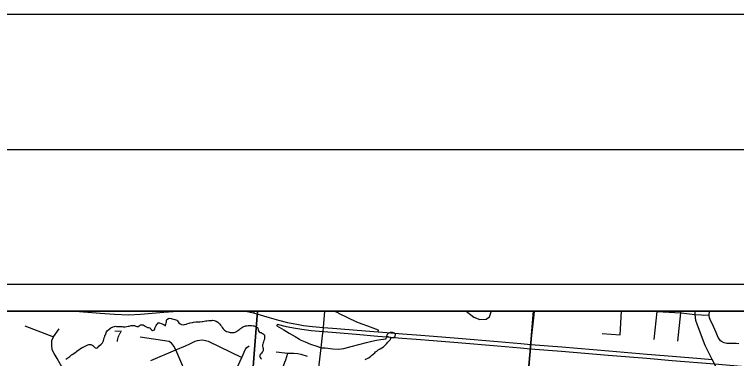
# Model space of a CAD drawing. Extents: x 0 to 34, y 0 to 22.
# Drawn here: x 3.964 to 6.638, y 20.725 to 22 of the extents above; entities that cross this region are included whole.
import ezdxf

# ---------------------------------------------------------------- set-up
doc = ezdxf.new("R2010")
doc.units = 0
for name, color, linetype in [('Default', 7, 'Continuous'), ('GM_X_Interchange_Ramps', 7, 'Continuous'), ('GM_X_Minor_River', 7, 'Continuous'), ('GM_X_Section_Text', 7, 'Continuous'), ('GM_X_State_Route', 7, 'Continuous'), ('GM_X_Township_Road', 7, 'Continuous'), ('SH_Border', 7, 'Continuous'), ('SH_Cut_Line', 7, 'Continuous'), ('SH_Data', 7, 'Continuous')]:
    doc.layers.add(name, color=color, linetype=linetype)

msp = doc.modelspace()

# ---------------------------------------------------------------- linework, layer by layer
at = {"layer": 'Default'}
for points in [[(4.8644, 20.9), (3.8452, 20.9), (3.806, 20.3918), (4.818, 20.3144)], [(5.8864, 20.9), (4.8644, 20.9), (4.818, 20.3144), (5.8084, 20.2412), (5.8307, 20.238)], [(6.92, 20.9), (5.8864, 20.9), (5.8307, 20.238), (6.8362, 20.1611), (6.8487, 20.1601)]]:
    msp.add_lwpolyline(points, close=True, dxfattribs=at)
at = {"layer": 'GM_X_Interchange_Ramps'}
for points in [[(4.9242, 20.9), (4.9177, 20.8994), (4.8932, 20.899), (4.8515, 20.8985), (4.8496, 20.8935)], [(5.1658, 20.8922), (5.1626, 20.8938), (5.1475, 20.9)], [(5.3117, 20.824), (5.3122, 20.8296), (5.2732, 20.8442), (5.2521, 20.8517), (5.2319, 20.8599), (5.1658, 20.8922)], [(4.9373, 20.8524), (4.9362, 20.8459), (4.9616, 20.8314), (4.9818, 20.8187), (5.0038, 20.8064), (5.0198, 20.7963)], [(5.0198, 20.7963), (5.0226, 20.7945), (5.041, 20.7862), (5.0604, 20.7779), (5.0836, 20.7709), (5.0995, 20.7643)], [(5.0995, 20.7643), (5.1148, 20.7647), (5.1433, 20.7603), (5.1639, 20.7594), (5.1845, 20.7616), (5.2113, 20.7687), (5.2679, 20.784), (5.2881, 20.7893), (5.3052, 20.7928), (5.3206, 20.7954), (5.3412, 20.7981), (5.3419, 20.8057)]]:
    msp.add_lwpolyline(points, dxfattribs=at)
at = {"layer": 'GM_X_Minor_River'}
for points in [[(4.4934, 20.8536), (4.4969, 20.8569), (4.5011, 20.8564), (4.5079, 20.8546), (4.5173, 20.8509), (4.5232, 20.8453), (4.5253, 20.8517), (4.5262, 20.8566), (4.5267, 20.8593), (4.5274, 20.8665), (4.5282, 20.8691), (4.5341, 20.8735), (4.5372, 20.8737), (4.5447, 20.8731), (4.5485, 20.8718), (4.5583, 20.8695), (4.5613, 20.8683), (4.5651, 20.8666), (4.5684, 20.8646), (4.571, 20.8611), (4.5731, 20.8576), (4.5775, 20.8532), (4.5828, 20.8507), (4.5911, 20.85), (4.5938, 20.8503), (4.5999, 20.852), (4.603, 20.853), (4.6111, 20.8558), (4.615, 20.8564), (4.6234, 20.8584), (4.6273, 20.8594), (4.6361, 20.8609), (4.6403, 20.8612), (4.6486, 20.8609), (4.6525, 20.8611), (4.6597, 20.862), (4.6624, 20.8622), (4.667, 20.8632), (4.6735, 20.8645), (4.6766, 20.8648), (4.6838, 20.8653), (4.6873, 20.8655), (4.6945, 20.866), (4.6972, 20.8663), (4.7036, 20.8657), (4.7116, 20.8631), (4.7171, 20.8591), (4.7234, 20.8531), (4.7277, 20.848), (4.7307, 20.8441), (4.7339, 20.8398), (4.7372, 20.8347), (4.7415, 20.8296), (4.749, 20.8252), (4.7558, 20.8234), (4.7592, 20.8221), (4.7633, 20.8216), (4.7682, 20.8207), (4.7732, 20.8212), (4.7774, 20.8218), (4.7813, 20.8228), (4.7859, 20.8246), (4.7886, 20.8264), (4.7914, 20.8286), (4.7945, 20.8311), (4.7973, 20.8329), (4.8016, 20.8366), (4.8086, 20.8412), (4.814, 20.8433), (4.8175, 20.8443), (4.8202, 20.8458), (4.8248, 20.8464), (4.8298, 20.8469), (4.834, 20.8468), (4.8393, 20.847), (4.8419, 20.8469), (4.848, 20.8463), (4.8522, 20.8453), (4.8548, 20.8445), (4.8593, 20.842), (4.8642, 20.84), (4.8656, 20.8369), (4.8665, 20.8303), (4.8675, 20.8269), (4.87, 20.8234), (4.8742, 20.8217), (4.8775, 20.8208), (4.8805, 20.8188), (4.8832, 20.8179), (4.8858, 20.8167), (4.8887, 20.8132), (4.8897, 20.8105), (4.8899, 20.8055), (4.8902, 20.8013), (4.8896, 20.7964), (4.8883, 20.7915), (4.8862, 20.7862), (4.8849, 20.7828), (4.8836, 20.7783), (4.8831, 20.7749), (4.8833, 20.7703)], [(4.1545, 20.7219), (4.162, 20.7273), (4.169, 20.7324), (4.1757, 20.7379), (4.1784, 20.7397), (4.1846, 20.7429), (4.1925, 20.749), (4.1956, 20.7516), (4.2039, 20.7581), (4.207, 20.7603), (4.2128, 20.7639), (4.2156, 20.7657), (4.221, 20.7685), (4.2237, 20.7692), (4.2284, 20.7721), (4.2365, 20.7752), (4.2392, 20.7766), (4.2438, 20.7772), (4.2464, 20.7764), (4.2502, 20.7755), (4.2547, 20.7726), (4.2587, 20.7694), (4.2631, 20.7647), (4.2677, 20.7634), (4.2715, 20.7648), (4.2782, 20.7714), (4.2857, 20.7783), (4.2905, 20.7831), (4.2934, 20.7906), (4.2955, 20.7962), (4.2968, 20.8011), (4.2973, 20.8038), (4.2986, 20.8068), (4.2994, 20.8098), (4.3015, 20.8128), (4.3027, 20.8158), (4.3049, 20.8233), (4.3073, 20.827), (4.3132, 20.8329), (4.3207, 20.8383), (4.3296, 20.8426), (4.3346, 20.8439), (4.3388, 20.8441), (4.3422, 20.844), (4.3468, 20.8435), (4.3509, 20.8429), (4.3627, 20.8429), (4.3673, 20.8423), (4.3719, 20.8425), (4.3745, 20.8428), (4.3807, 20.8433), (4.3856, 20.8443), (4.3891, 20.8449), (4.3929, 20.8456), (4.3964, 20.8466), (4.4006, 20.8472), (4.4044, 20.8474), (4.4082, 20.8469), (4.4108, 20.8457), (4.4138, 20.8448), (4.4176, 20.8439), (4.4218, 20.843), (4.4257, 20.8459), (4.4288, 20.8477), (4.4315, 20.8491), (4.4376, 20.8496), (4.4407, 20.8495), (4.4485, 20.8446), (4.4567, 20.8402), (4.4601, 20.8393), (4.4639, 20.8384), (4.4665, 20.8383), (4.4679, 20.8352), (4.4716, 20.8312), (4.4757, 20.8292), (4.4795, 20.8294), (4.4826, 20.8312), (4.4835, 20.8346), (4.484, 20.8376), (4.4861, 20.8417), (4.4886, 20.8477), (4.491, 20.8503), (4.4934, 20.8536)], [(5.3594, 20.8025), (5.3697, 20.8028), (5.3716, 20.8047), (5.3736, 20.8069), (5.3757, 20.8144), (5.372, 20.8191), (5.3637, 20.8208), (5.3554, 20.8218), (5.3484, 20.817), (5.3445, 20.8141), (5.343, 20.8119), (5.3421, 20.8096)], [(5.3421, 20.8096), (5.3455, 20.8073), (5.3496, 20.8056), (5.3594, 20.8025)], [(5.3252, 20.7647), (5.3303, 20.7683), (5.3346, 20.772), (5.3378, 20.7749), (5.3425, 20.7797), (5.3473, 20.7856), (5.3524, 20.7903), (5.3552, 20.7937), (5.3572, 20.7962), (5.3577, 20.7997), (5.3594, 20.8023), (5.3594, 20.8025)], [(4.8833, 20.7703), (4.8843, 20.7654), (4.8853, 20.7623), (4.8858, 20.7569), (4.8857, 20.7535), (4.8841, 20.7509), (4.8817, 20.7483), (4.8789, 20.7446), (4.8754, 20.7413), (4.8726, 20.7376), (4.8721, 20.7346), (4.8731, 20.7315), (4.8745, 20.7284), (4.8763, 20.7249), (4.8788, 20.7218)], [(5.2634, 20.7213), (5.2759, 20.7277), (5.2809, 20.7309), (5.2864, 20.7357), (5.2931, 20.7415), (5.2986, 20.7455), (5.3018, 20.7492), (5.3065, 20.7524), (5.3116, 20.7564), (5.3182, 20.7611), (5.3252, 20.7647)]]:
    msp.add_lwpolyline(points, dxfattribs=at)
at = {"layer": 'GM_X_State_Route'}
for points in [[(4.1953, 20.9), (4.2049, 20.8992), (4.282, 20.8929), (4.3352, 20.8891), (4.3872, 20.8872), (4.4306, 20.8886), (4.4738, 20.8923), (4.5174, 20.896), (4.5513, 20.8992), (4.5611, 20.9)], [(4.8203, 20.9), (4.8496, 20.8935), (4.865, 20.8889), (4.9073, 20.877), (4.9426, 20.8667), (4.9754, 20.8583), (5.0102, 20.8517), (5.0343, 20.8474), (5.0681, 20.8433), (5.1085, 20.84), (5.1579, 20.8365), (5.2328, 20.8301), (5.3117, 20.824), (5.3434, 20.8216), (5.401, 20.8166), (5.4535, 20.8122), (5.5162, 20.8073), (5.6072, 20.7997), (5.754, 20.7877), (5.8399, 20.7806), (5.8768, 20.7771), (5.9911, 20.7678), (6.1648, 20.7535), (6.3077, 20.7415), (6.4013, 20.7338), (6.5058, 20.7249), (6.5479, 20.7215)], [(5.1065, 20.8198), (5.1072, 20.8253), (5.1085, 20.84), (5.1141, 20.9)], [(4.9373, 20.8524), (4.9701, 20.8439), (5.0049, 20.8373), (5.029, 20.833), (5.0628, 20.8289), (5.1072, 20.8253), (5.11, 20.8251)], [(5.0926, 20.6654), (5.0932, 20.7009), (5.0995, 20.7643), (5.1065, 20.8198)], [(5.11, 20.8251), (5.155, 20.821), (5.23, 20.8148), (5.3102, 20.8082), (5.3419, 20.8057), (5.3996, 20.8008), (5.452, 20.7964), (5.5147, 20.7914), (5.6057, 20.7839), (5.7526, 20.7719), (5.8384, 20.7648), (5.8751, 20.7612), (5.9896, 20.752), (6.1633, 20.7377), (6.3063, 20.7257), (6.3999, 20.7179), (6.5561, 20.7048), (6.7287, 20.6902)]]:
    msp.add_lwpolyline(points, dxfattribs=at)
at = {"layer": 'GM_X_Township_Road'}
for p, q in [((5.8889, 20.8867), (5.8903, 20.9)), ((4.0026, 20.8454), (4.1089, 20.8046)), ((4.1219, 20.7251), (4.1118, 20.7429)), ((4.1676, 20.6452), (4.1219, 20.7251))]:
    msp.add_line(p, q, dxfattribs=at)
for points in [[(8.9, 20.9), (3.8479, 20.9)], [(5.6366, 20.9), (5.6653, 20.8778), (5.6872, 20.8695), (5.7106, 20.871), (5.7234, 20.8793), (5.7294, 20.8982), (5.7297, 20.9)], [(5.8644, 20.6498), (5.8664, 20.6709), (5.8751, 20.7612), (5.8768, 20.7771), (5.8889, 20.8867)], [(6.1409, 20.8174), (6.2078, 20.8127), (6.2124, 20.9)], [(6.3334, 20.7957), (6.3443, 20.8996), (6.3443, 20.9)], [(6.3408, 20.9), (6.3443, 20.8996), (6.4321, 20.8936), (6.4847, 20.8884)], [(6.4214, 20.7895), (6.4321, 20.8936), (6.4325, 20.9)], [(6.494, 20.8479), (6.4875, 20.8652), (6.4847, 20.8884), (6.4852, 20.9)], [(6.4847, 20.8884), (6.508, 20.8865), (6.5174, 20.8857), (6.5369, 20.8863)], [(6.6468, 20.7795), (6.6368, 20.7799), (6.6163, 20.7805), (6.602, 20.7809), (6.5971, 20.7816), (6.5923, 20.783), (6.5872, 20.7852), (6.5829, 20.7878), (6.579, 20.7909), (6.576, 20.794), (6.5734, 20.7975), (6.5705, 20.803), (6.5676, 20.8094), (6.5623, 20.8211), (6.5526, 20.8435), (6.541, 20.8688), (6.5386, 20.8752), (6.5378, 20.8779), (6.5373, 20.8806), (6.537, 20.8841), (6.5369, 20.8863), (6.5377, 20.9)], [(4.1118, 20.7429), (4.1036, 20.7571), (4.1021, 20.776), (4.1021, 20.7911), (4.1089, 20.8046), (4.1293, 20.8348)], [(6.591, 20.632), (6.5721, 20.6727), (6.5561, 20.7048), (6.5479, 20.7215), (6.5224, 20.7731), (6.494, 20.8479)], [(4.6317, 20.3309), (4.6345, 20.382), (4.6356, 20.4023), (4.6392, 20.4582), (4.642, 20.471), (4.6402, 20.5089), (4.6359, 20.5297), (4.6239, 20.6003), (4.6206, 20.6161), (4.6129, 20.6389), (4.5614, 20.7566), (4.5549, 20.7708), (4.5465, 20.7808), (4.5365, 20.7875), (4.4291, 20.8041)], [(4.4694, 20.7171), (4.5614, 20.7566), (4.5973, 20.772), (4.6134, 20.7795), (4.6334, 20.7886), (4.6424, 20.7916), (4.6502, 20.793), (4.6618, 20.7934), (4.6812, 20.7894), (4.8068, 20.7283)], [(4.7847, 20.3615), (4.7981, 20.5233), (4.7984, 20.5491), (4.7856, 20.632), (4.7826, 20.6483), (4.7812, 20.6586), (4.7812, 20.6724), (4.7835, 20.68), (4.8068, 20.7283), (4.8201, 20.7588), (4.8243, 20.765), (4.8329, 20.7714)], [(4.8599, 20.3131), (4.8636, 20.3659), (4.8688, 20.4412), (4.8752, 20.5174), (4.8771, 20.5326), (4.8782, 20.5402), (4.8803, 20.5475), (4.885, 20.5563), (4.8915, 20.5637), (4.8963, 20.5679), (4.903, 20.5747), (4.9076, 20.5796), (4.9136, 20.5858), (4.9189, 20.5957), (4.9353, 20.6335), (4.951, 20.674), (4.9605, 20.6977), (4.9651, 20.7111), (4.9692, 20.7205), (4.9767, 20.7443)], [(4.933, 20.7492), (4.9767, 20.7443), (4.9989, 20.7442), (5.0134, 20.7431), (5.0247, 20.7403), (5.0476, 20.733)]]:
    msp.add_lwpolyline(points, dxfattribs=at)
at = {"layer": 'SH_Border'}
msp.add_lwpolyline([(1.5, 21.5), (33.5, 21.5), (33.5, 0.5), (1.5, 0.5)], close=True, dxfattribs=at)
at = {"layer": 'SH_Cut_Line'}
msp.add_lwpolyline([(0, 0), (34, 0), (34, 22), (0, 22)], close=True, dxfattribs=at)
msp.add_lwpolyline([(8.9, 14.8595), (8.9, 20.9), (2.1, 20.9), (2.1, 19.3633)], dxfattribs=at)
at = {"layer": 'SH_Data'}
for p, q in [((2, 21), (9, 21)), ((2.1, 20.9), (8.9, 20.9))]:
    msp.add_line(p, q, dxfattribs=at)

# ---------------------------------------------------------------- texts
at = {"layer": 'GM_X_Section_Text'}
msp.add_text('7', height=0.0419, rotation=0, dxfattribs=at).set_placement((4.3325, 20.7866))

doc.saveas('drawing.dxf')
